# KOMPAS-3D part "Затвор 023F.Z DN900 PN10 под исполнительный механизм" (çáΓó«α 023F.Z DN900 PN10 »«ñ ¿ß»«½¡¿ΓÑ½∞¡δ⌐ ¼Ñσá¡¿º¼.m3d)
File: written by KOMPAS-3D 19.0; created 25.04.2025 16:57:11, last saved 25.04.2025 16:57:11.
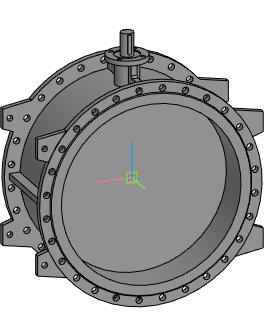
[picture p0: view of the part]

Document properties: Автор: Евгений; Полное имя файла: E:\Dendor Работа Сачек\3D для проекитирвщиков\1.7 Тип 023F.Z Затвор дисковый поворотный фланцевый с двумя эксцентриками\stp_Тип 023F.Z. Затвор под исполн. механизм\Затвор 023F.Z DN900 PN10 под исполнительный механизм.m3d

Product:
- Part/product: Затвор 023F.Z DN900 PN10 под исполнительный механизм

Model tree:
1. Операция без истории:1  (labels: Затвор 023F.Z DN900 PN10 под исполнительный механизм)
